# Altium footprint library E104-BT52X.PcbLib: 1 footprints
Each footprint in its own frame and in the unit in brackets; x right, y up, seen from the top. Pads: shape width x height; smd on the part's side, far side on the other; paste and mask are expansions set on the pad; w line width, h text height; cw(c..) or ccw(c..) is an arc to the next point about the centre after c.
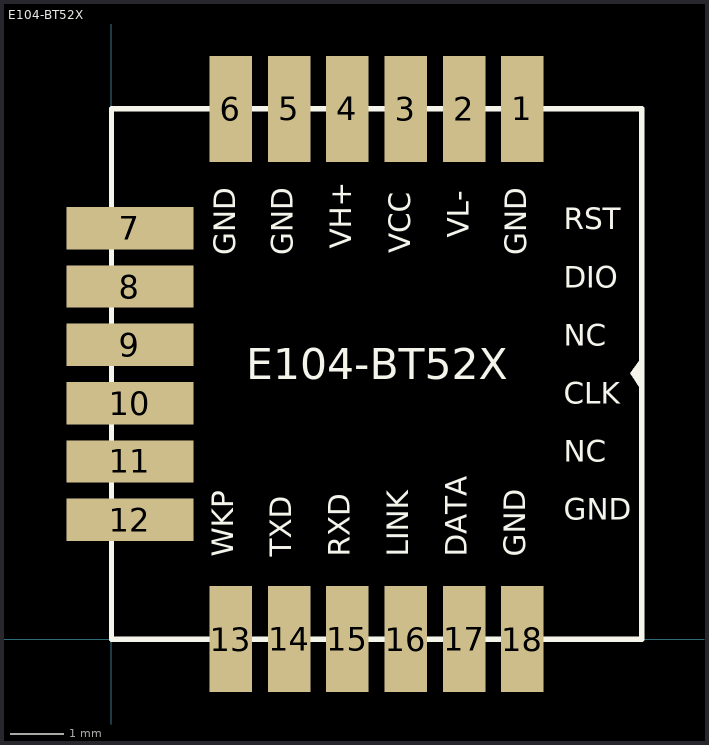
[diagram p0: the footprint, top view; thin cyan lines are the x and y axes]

## E104-BT52X [mm]
pads (18):
  rect 0.8x2 smd: 1(7.75,10) 2(6.65,10) 3(5.55,10) 4(4.45,10) 5(3.35,10) 6(2.25,10) 13(2.25,0) 14(3.35,0) 15(4.45,0) 16(5.55,0) 17(6.65,0) 18(7.75,0)
  rect 2.4x0.8 smd: 7(0.349,7.75) 8(0.349,6.65) 9(0.349,5.55) 10(0.349,4.45) 11(0.349,3.35) 12(0.349,2.25)
Top Overlay:
  region: 9.779,5.016 10,4.683 10,5.318
  lines w0.1: 0,0 10,0 10,10 0,10 0,0
  text "VL-" at 6.878,7.566 h0.7
  text "GND" at 2.472,7.24 h0.7
  text "WKP" at 2.437,1.556 h0.7
  text "GND" at 7.946,1.556 h0.7
  text "DATA" at 6.844,1.556 h0.7
  text "RXD" at 4.632,1.556 h0.7
  text "TXD" at 3.531,1.556 h0.7
  text "GND" at 7.968,7.24 h0.7
  text "VCC" at 5.777,7.28 h0.7
  text "VH+" at 4.663,7.361 h0.7
  text "GND" at 3.565,7.24 h0.7
  text "RST" at 8.525,7.585 h0.7
  text "DIO" at 8.525,6.489 h0.7
  text "NC" at 8.525,5.394 h0.7
  text "CLK" at 8.525,4.298 h0.7
  text "NC" at 8.525,3.203 h0.7
  text "GND" at 8.525,2.107 h0.7
  text "LINK" at 5.734,1.556 h0.7
  text "E104-BT52X" at 2.54,4.699 h1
